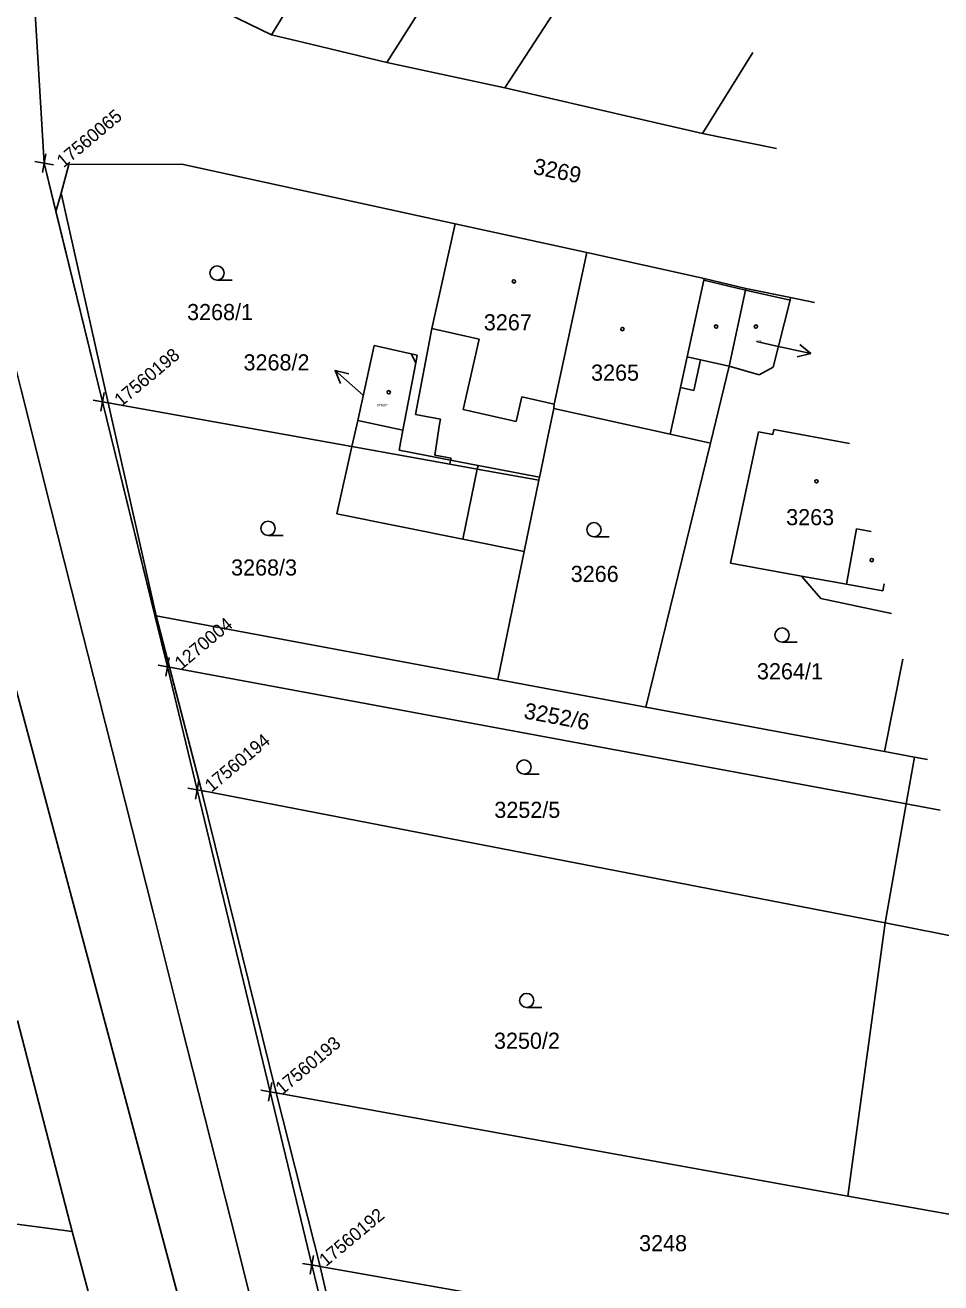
# Model space of a CAD drawing. Extents: x -754679 to -754173, y -1169241 to -1168288.
# Drawn here: x -754379.7 to -754307.2, y -1169048.7 to -1168949.2 of the extents above; entities that cross this region are included whole.
import ezdxf

# ---------------------------------------------------------------- set-up
doc = ezdxf.new("R2010")
doc.units = 0
for name, color, linetype in [('Vrstva 1', 7, 'Continuous'), ('Vrstva 16', 7, 'Continuous'), ('Vrstva 18', 7, 'Continuous'), ('Vrstva 19', 7, 'Continuous'), ('Vrstva 25', 7, 'Continuous'), ('Vrstva 4', 7, 'Continuous'), ('Vrstva 52', 7, 'Continuous'), ('Vrstva 53', 7, 'Continuous'), ('Vrstva 6', 7, 'Continuous'), ('Vrstva 60', 7, 'Continuous')]:
    doc.layers.add(name, color=color, linetype=linetype)

msp = doc.modelspace()

# ---------------------------------------------------------------- linework, layer by layer
at = {"layer": 'Vrstva 1'}
for p, q in [((-754351.06, -1168952.16), (-754336.53, -1168929.23)), ((-754348.61, -1168930.98), (-754360.17, -1168949.97)), ((-754341.72, -1168954.18), (-754327.021, -1168931.533)), ((-754372.18, -1168944.13), (-754360.17, -1168949.97)), ((-754379.05, -1168945.33), (-754378.16, -1168960.13)), ((-754360.17, -1168949.97), (-754357.06, -1168950.72)), ((-754357.06, -1168950.72), (-754351.06, -1168952.16)), ((-754326.09, -1168957.79), (-754322.118, -1168951.362)), ((-754351.06, -1168952.16), (-754341.72, -1168954.18)), ((-754331.48, -1168956.55), (-754341.72, -1168954.18)), ((-754326.09, -1168957.79), (-754331.48, -1168956.55)), ((-754320.237, -1168958.968), (-754326.09, -1168957.79)), ((-754378.16, -1168960.13), (-754377.23, -1168963.95)), ((-754376.2, -1168960.23), (-754376.82, -1168962.5)), ((-754367.27, -1168960.2), (-754376.2, -1168960.23)), ((-754367.27, -1168960.2), (-754345.64, -1168964.92)), ((-754376.82, -1168962.5), (-754377.23, -1168963.95)), ((-754377.23, -1168963.95), (-754373.54, -1168979.01)), ((-754345.64, -1168964.92), (-754347.5, -1168973.21)), ((-754345.64, -1168964.92), (-754335.23, -1168967.19)), ((-754335.23, -1168967.19), (-754337.82, -1168979.18)), ((-754325.95, -1168969.24), (-754335.23, -1168967.19)), ((-754322.66, -1168970.03), (-754325.95, -1168969.24)), ((-754322.69, -1168970.17), (-754323.97, -1168976.18)), ((-754322.66, -1168970.03), (-754322.69, -1168970.17)), ((-754319.13, -1168970.76), (-754322.66, -1168970.03)), ((-754319.17, -1168970.96), (-754320.49, -1168976.26)), ((-754319.13, -1168970.76), (-754319.17, -1168970.96)), ((-754317.223, -1168971.156), (-754319.13, -1168970.76)), ((-754347.5, -1168973.21), (-754348.8, -1168980)), ((-754353.36, -1168980.47), (-754352.07, -1168974.56)), ((-754352.07, -1168974.56), (-754349.14, -1168975.2)), ((-754348.65, -1168975.31), (-754349.14, -1168975.2)), ((-754348.65, -1168975.31), (-754348.76, -1168975.91)), ((-754349.78, -1168981.25), (-754348.76, -1168975.91)), ((-754323.97, -1168976.18), (-754325.46, -1168982.26)), ((-754321.62, -1168976.87), (-754323.97, -1168976.18)), ((-754320.49, -1168976.26), (-754321.62, -1168976.87)), ((-754369.4, -1168995.91), (-754373.54, -1168979.01)), ((-754337.82, -1168979.18), (-754337.86, -1168979.53)), ((-754348.8, -1168980), (-754346.82, -1168980.37)), ((-754346.88, -1168980.76), (-754346.82, -1168980.37)), ((-754338.32, -1168981.76), (-754337.86, -1168979.53)), ((-754337.86, -1168979.53), (-754328.65, -1168981.56)), ((-754386.06, -1168980.52), (-754345.91, -1169130.8)), ((-754349.78, -1168981.25), (-754353.36, -1168980.47)), ((-754347.26, -1168983.23), (-754346.88, -1168980.76)), ((-754321.66, -1168981.38), (-754323.88, -1168991.76)), ((-754320.54, -1168981.59), (-754321.66, -1168981.38)), ((-754320.46, -1168981.2), (-754320.54, -1168981.59)), ((-754314.468, -1168982.298), (-754320.46, -1168981.2)), ((-754338.91, -1168984.63), (-754338.32, -1168981.76)), ((-754325.46, -1168982.26), (-754330.56, -1169003.14)), ((-754325.46, -1168982.26), (-754328.65, -1168981.56)), ((-754345.98, -1168983.45), (-754347.26, -1168983.23)), ((-754346.01, -1168983.62), (-754346.07, -1168983.93)), ((-754346.01, -1168983.62), (-754345.98, -1168983.45)), ((-754339.03, -1168985.19), (-754340.19, -1168990.83)), ((-754339.03, -1168985.19), (-754338.98, -1168984.96)), ((-754338.91, -1168984.63), (-754338.98, -1168984.96)), ((-754342.29, -1169000.96), (-754340.19, -1168990.83)), ((-754323.88, -1168991.76), (-754318.27, -1168992.78)), ((-754318.27, -1168992.78), (-754316.73, -1168994.57)), ((-754316.73, -1168994.57), (-754311.143, -1168995.745)), ((-754369.4, -1168995.91), (-754369.3, -1168995.93)), ((-754368.41, -1168999.96), (-754369.4, -1168995.91)), ((-754369.3, -1168995.93), (-754342.29, -1169000.96)), ((-754368.41, -1168999.96), (-754366.06, -1169009.68)), ((-754309.98, -1169010.8), (-754368.25, -1168999.99)), ((-754310.251, -1168999.35), (-754311.7, -1169006.65)), ((-754330.56, -1169003.14), (-754342.29, -1169000.96)), ((-754311.7, -1169006.65), (-754330.56, -1169003.14)), ((-754309.32, -1169007.1), (-754311.7, -1169006.65)), ((-754309.98, -1169010.8), (-754309.32, -1169007.1)), ((-754309.32, -1169007.1), (-754308.287, -1169007.295)), ((-754366.06, -1169009.68), (-754360.29, -1169033.58)), ((-754365.72, -1169009.75), (-754366.06, -1169009.68)), ((-754311.65, -1169020.21), (-754365.72, -1169009.75)), ((-754311.65, -1169020.21), (-754309.98, -1169010.8)), ((-754309.98, -1169010.8), (-754307.297, -1169011.298)), ((-754314.59, -1169041.82), (-754311.65, -1169020.21)), ((-754311.65, -1169020.21), (-754304.757, -1169021.57)), ((-754380.27, -1169027.93), (-754375.93, -1169044.62)), ((-754359.82, -1169033.66), (-754360.29, -1169033.58)), ((-754360.29, -1169033.58), (-754356.98, -1169047.27)), ((-754314.59, -1169041.82), (-754359.82, -1169033.66)), ((-754411.85, -1169039.94), (-754375.93, -1169044.62)), ((-754299.056, -1169044.622), (-754314.59, -1169041.82)), ((-754375.93, -1169044.62), (-754373.03, -1169055.57)), ((-754356.98, -1169047.27), (-754356.33, -1169047.39)), ((-754356.98, -1169047.27), (-754354.28, -1169058.43)), ((-754295.737, -1169058.045), (-754356.33, -1169047.39))]:
    msp.add_line(p, q, dxfattribs=at)
for points in [[(-754371.756, -1169010.617), (-754373.805, -1169002.503), (-754376.012, -1168993.767), (-754377.617, -1168987.413), (-754379.98, -1168978.062), (-754382.327, -1168968.778)], [(-754354.862, -1169077.498), (-754356.926, -1169069.332), (-754359.117, -1169060.65), (-754361.326, -1169051.908), (-754363.428, -1169043.592), (-754365, -1169037.372), (-754367.338, -1169028.11), (-754369.544, -1169019.374), (-754371.756, -1169010.617)]]:
    msp.add_lwpolyline(points, dxfattribs=at)
at = {"layer": 'Vrstva 16'}
for p, q in [((-754321.83, -1168974.24), (-754320.46, -1168974.54)), ((-754317.529, -1168975.181), (-754320.46, -1168974.54)), ((-754355.148, -1168976.515), (-754352.89, -1168978.49))]:
    msp.add_line(p, q, dxfattribs=at)
for points in [[(-754318.399, -1168974.479), (-754317.529, -1168975.181), (-754318.613, -1168975.456)], [(-754354.724, -1168977.549), (-754355.148, -1168976.515), (-754354.066, -1168976.797)]]:
    msp.add_lwpolyline(points, dxfattribs=at)
at = {"layer": 'Vrstva 25'}
for p, q in [((-754364.48, -1168969.38), (-754363.28, -1168969.38)), ((-754360.45, -1168989.57), (-754359.25, -1168989.57)), ((-754334.68, -1168989.68), (-754333.48, -1168989.68)), ((-754319.8, -1168998.01), (-754318.6, -1168998.01)), ((-754340.2, -1169008.45), (-754339, -1169008.45)), ((-754339.99, -1169026.91), (-754338.79, -1169026.91))]:
    msp.add_line(p, q, dxfattribs=at)
for centre, radius in [((-754364.48, -1168968.818), 0.562), ((-754341.01, -1168969.48), 0.131), ((-754332.42, -1168973.25), 0.131), ((-754325.02, -1168973.05), 0.131), ((-754321.87, -1168973.05), 0.131), ((-754350.91, -1168978.25), 0.131), ((-754317.08, -1168985.29), 0.131), ((-754360.45, -1168989.008), 0.562), ((-754334.68, -1168989.117), 0.562), ((-754312.7, -1168991.52), 0.131), ((-754319.8, -1168997.448), 0.562), ((-754340.2, -1169007.887), 0.562), ((-754339.99, -1169026.347), 0.562)]:
    msp.add_circle(centre, radius, dxfattribs=at)
at = {"layer": 'Vrstva 4'}
for p, q in [((-754373.09, -1168979.09), (-754376.82, -1168962.5)), ((-754327.31, -1168975.45), (-754325.98, -1168969.38)), ((-754325.98, -1168969.38), (-754325.95, -1168969.24)), ((-754325.98, -1168969.38), (-754322.69, -1168970.17)), ((-754322.69, -1168970.17), (-754319.17, -1168970.96)), ((-754347.5, -1168973.21), (-754343.76, -1168974.05)), ((-754343.76, -1168974.05), (-754345.01, -1168979.62)), ((-754349.14, -1168975.2), (-754348.76, -1168975.91)), ((-754327.31, -1168975.45), (-754327.84, -1168977.87)), ((-754326.24, -1168975.68), (-754327.31, -1168975.45)), ((-754326.24, -1168975.68), (-754326.77, -1168978.11)), ((-754323.97, -1168976.18), (-754326.24, -1168975.68)), ((-754327.84, -1168977.87), (-754328.65, -1168981.56)), ((-754326.77, -1168978.11), (-754327.84, -1168977.87)), ((-754369.3, -1168995.93), (-754373.09, -1168979.09)), ((-754340.82, -1168980.56), (-754340.38, -1168978.61)), ((-754340.38, -1168978.61), (-754337.82, -1168979.18)), ((-754345.01, -1168979.62), (-754340.82, -1168980.56)), ((-754353.36, -1168980.47), (-754353.83, -1168982.54)), ((-754349.78, -1168981.25), (-754350.09, -1168982.83)), ((-754353.83, -1168982.54), (-754355.02, -1168987.85)), ((-754350.09, -1168982.83), (-754346.01, -1168983.62)), ((-754343.84, -1168984.04), (-754346.01, -1168983.62)), ((-754345.04, -1168989.86), (-754343.9, -1168984.32)), ((-754343.84, -1168984.04), (-754343.9, -1168984.32)), ((-754343.84, -1168984.04), (-754338.98, -1168984.96)), ((-754355.02, -1168987.85), (-754345.04, -1168989.86)), ((-754313.9, -1168989.06), (-754314.69, -1168993.43)), ((-754312.745, -1168989.265), (-754313.9, -1168989.06)), ((-754345.04, -1168989.86), (-754340.19, -1168990.83)), ((-754314.69, -1168993.43), (-754318.27, -1168992.78)), ((-754311.82, -1168993.95), (-754314.69, -1168993.43)), ((-754311.722, -1168993.404), (-754311.82, -1168993.95)), ((-754368.25, -1168999.99), (-754369.3, -1168995.93)), ((-754368.25, -1168999.99), (-754365.72, -1169009.75)), ((-754359.82, -1169033.66), (-754365.72, -1169009.75)), ((-754356.33, -1169047.39), (-754359.82, -1169033.66)), ((-754353.72, -1169058.53), (-754356.33, -1169047.39))]:
    msp.add_line(p, q, dxfattribs=at)
at = {"layer": 'Vrstva 53'}
for p, q in [((-754379.05, -1168945.33), (-754378.16, -1168960.13)), ((-754378.16, -1168960.13), (-754373.54, -1168979.01)), ((-754373.54, -1168979.01), (-754368.41, -1168999.96)), ((-754368.41, -1168999.96), (-754366.06, -1169009.68)), ((-754366.06, -1169009.68), (-754360.29, -1169033.58)), ((-754360.29, -1169033.58), (-754356.98, -1169047.27))]:
    msp.add_line(p, q, dxfattribs=at)
msp.add_lwpolyline([(-754345.91, -1169130.8), (-754386.06, -1168980.52), (-754394.57, -1168948.26)], dxfattribs=at)
at = {"layer": 'Vrstva 6'}
for p, q in [((-754373.54, -1168979.01), (-754373.09, -1168979.09)), ((-754373.09, -1168979.09), (-754353.83, -1168982.54)), ((-754346.07, -1168983.93), (-754353.83, -1168982.54)), ((-754346.07, -1168983.93), (-754343.9, -1168984.32)), ((-754343.9, -1168984.32), (-754339.03, -1168985.19)), ((-754368.41, -1168999.96), (-754368.25, -1168999.99))]:
    msp.add_line(p, q, dxfattribs=at)
at = {"layer": 'Vrstva 60'}
for p, q in [((-754378.03, -1168959.391), (-754378.29, -1168960.869)), ((-754378.899, -1168960), (-754377.421, -1168960.26)), ((-754373.41, -1168978.271), (-754373.67, -1168979.749)), ((-754374.279, -1168978.88), (-754372.801, -1168979.14)), ((-754368.28, -1168999.221), (-754368.54, -1169000.699)), ((-754369.149, -1168999.83), (-754367.671, -1169000.09)), ((-754365.93, -1169008.941), (-754366.19, -1169010.419)), ((-754366.799, -1169009.55), (-754365.321, -1169009.81)), ((-754360.16, -1169032.841), (-754360.42, -1169034.319)), ((-754361.029, -1169033.45), (-754359.551, -1169033.71)), ((-754356.85, -1169046.531), (-754357.11, -1169048.009)), ((-754357.719, -1169047.14), (-754356.241, -1169047.4))]:
    msp.add_line(p, q, dxfattribs=at)

# ---------------------------------------------------------------- texts
at = {"layer": 'Vrstva 16'}
msp.add_text('3268/2', height=1.275, rotation=360, dxfattribs=at).set_placement((-754362.39, -1168976.52))
at = {"layer": 'Vrstva 18'}
for s, rotation, p in [('3269', 348.30104, (-754339.553, -1168960.962)), ('3268/1', 360, (-754366.853, -1168972.54)), ('3268/3', 360, (-754363.373, -1168992.74)), ('3266', 360, (-754336.513, -1168993.25)), ('3264/1', 360, (-754321.784, -1169000.95)), ('3252/6', 349.50426, (-754340.286, -1169004.029)), ('3252/5', 360, (-754342.555, -1169011.91)), ('3250/2', 360, (-754342.583, -1169030.17)), ('3248', 360, (-754331.106, -1169046.181))]:
    msp.add_text(s, height=1.275, rotation=rotation, dxfattribs=at).set_placement(p)
at = {"layer": 'Vrstva 19'}
for s, p in [('3267', (-754343.383, -1168973.35)), ('3265', (-754334.903, -1168977.33)), ('3263', (-754319.473, -1168988.76))]:
    msp.add_text(s, height=1.275, rotation=360, dxfattribs=at).set_placement(p)
for s, height, p in [('3264/2', 0.1, (-754321.816, -1168974.24)), ('3268/2', 0.2, (-754351.852, -1168979.37))]:
    msp.add_text(s, height=height, dxfattribs=at).set_placement(p)
at = {"layer": 'Vrstva 52'}
for s, p in [(' 17560065', (-754376.923, -1168960.783)), (' 17560198', (-754372.365, -1168979.679)), (' 1270004', (-754367.59, -1169000.477)), (' 17560194', (-754365.212, -1169010.173)), (' 17560193', (-754359.631, -1169034.106)), (' 17560192', (-754356.169, -1169047.693))]:
    msp.add_text(s, height=1.0368, rotation=40, dxfattribs=at).set_placement(p)

doc.saveas('drawing.dxf')
